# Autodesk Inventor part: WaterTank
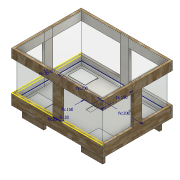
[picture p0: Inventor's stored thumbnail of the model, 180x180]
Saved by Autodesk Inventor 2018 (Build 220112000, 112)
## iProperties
Created: 2018-05
Part Number: WaterTank
Material: Generic
Document SubType Name: Modeling
Designer: arivu
Density: 1 g/cm^3
Appearance: Default
Author: arivu
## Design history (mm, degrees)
workplane "Work Plane2"
workplane "Work Plane4"
sketch "Sketch1"
  geometry: L1 (-200, 150)-(200, 150); L2 (200, 150)-(200, -150); L3 (200, -150)-(-200, -150); L4 (-200, -150)-(-200, 150); 1 further point
  constraints: 8 end point, 2 parallel, 1 horizontal, 1 perpendicular
  dimensions: "d0" = 200 distance from line of point (0, 0) L4 (= 0.5 x width); "d1" = 200 distance from line of L2 point (0, 0) (= d0); "d2" = 150 distance from line of L3 point (0, 0) (= 0.5 x height); "d3" = 150 distance from line of L1 point (0, 0) (= d2)
extrude "Extrusion1" new body sketch "Sketch1" distance "d4" = 200 (= depth); taper "d5" = 0 deg
sketch "Sketch2"
  geometry: L1 (-200, 150)-(200, 150) reference; L2 (200, -150)-(-200, -150); L3 (-200, -150)-(-200, 150); L4 (-200, 150)-(200, 150); L5 (200, 150)-(200, -150); L6 (212, -162)-(-212, -162); L7 (-212, -162)-(-212, 162); L8 (-212, 162)-(212, 162); L9 (212, 162)-(212, -162); 1 further point
  constraints: 16 end point, 4 parallel, 2 horizontal, 2 perpendicular
  dimensions: "d19" = 12 distance between parallel lines of L5 L9 (computed from osb); "d20" = 12 distance between parallel lines of L2 L6 (computed from osb); "d21" = 12 distance between parallel lines of L7 L3 (computed from osb); "d22" = 12 distance between parallel lines of L8 L1 (computed from osb)
extrude "Extrusion2" new body sketch "Sketch2" distance "d7" = 11 (= osb); taper "d8" = 0 deg
sketch "Sketch3"
  geometry: L1 (187, 137)-(87, 137); L2 (87, 137)-(87, 126); L3 (87, 126)-(187, 126); L4 (187, 126)-(187, 137); L5 (212, 162)-(-212, 162) reference; L6 (212, -162)-(212, 162) reference
  constraints: 8 end point, 2 parallel, 1 horizontal, 1 perpendicular
  dimensions: "d214" = 100 distance of L3.end L2.end; "d215" = 11 distance of L2.end L1.end (derived); "d216" = 25 distance between parallel lines of L1 L5; "d217" = 25 distance between parallel lines of L6 L4
extrude "Extrusion3" new body sketch "Sketch3" distance "d17" = 50 (= leg_lenght); taper "d18" = 0 deg
sketch "Sketch4"
  geometry: L1 (-212, -162)-(-212, 162) reference; L2 (212, -162)-(-212, -162) reference; L3 (-212, 162)-(212, 162); L4 (212, 162)-(212, -162); L5 (212, -162)-(-212, -162); L6 (-212, -162)-(-212, 162); L7 (-201, 151)-(201, 151); L8 (201, 151)-(201, -151); L9 (201, -151)-(-201, -151); L10 (-201, -151)-(-201, 151); 1 further point
  constraints: 16 end point, 4 parallel, 2 horizontal, 2 perpendicular
  dimensions: "d23" = 11 distance between parallel lines of L7 L3 (= osb); "d25" = 11 distance between parallel lines of L10 L1 (= osb); "d26" = 11 distance between parallel lines of L2 L9 (= osb); "d27" = 11 distance between parallel lines of L4 L8 (= osb)
extrude "Extrusion4" new body sketch "Sketch4" distance "d28" = 40; taper "d29" = 0 deg
sketch "Sketch5"
  geometry: L1 (0, 0)-(10.7, 0); L2 (0, 0)-(-10.7, 0); L3 (0, 0)-(0, 17.3); L4 (0, 0)-(0, -17.3); L5 (-10.7, 0)-(-10.7, 17.3); L6 (-10.7, 17.3)-(0, 17.3); L7 (0, 17.3)-(10.7, 17.3); L8 (10.7, 17.3)-(10.7, 0); L9 (10.7, -17.3)-(0, -17.3); L10 (10.7, 0)-(10.7, -17.3); L11 (0, -17.3)-(-10.7, -17.3); L12 (-10.7, -17.3)-(-10.7, 0); L13 (-161, 111)-(-143, 111); L14 (201, 151)-(-201, 151) reference; L15 (-201, 151)-(-201, -151) reference; C1 r 2.6 at (-161, 111); C2 r 2.6 at (-143, 111); C3 r 2.6 at (-161, -110); C4 r 2.6 at (-143, -110); C5 r 2.6 at (142, 111); C6 r 2.6 at (160, 111); C7 r 2.6 at (142, -110); C8 r 2.6 at (160, -110); 6 further points
  constraints: 26 end point, 8 centre point, 7 point on line, 5 horizontal, 4 perpendicular, 4 vertical, 2 coincident, 12 other
  dimensions: "d30" = 10.7 distance of L1.start L1.end; "d31" = 10.7 distance of L1.start L2.end; "d32" = 17.3 distance of L1.start L3.end; "d33" = 17.3 distance of L1.start L4.end; "d34" = 5.2 diameter of C1; "d35" = 18 distance of L13.start L13.end; "d36" = 5.2 diameter of C2; "d237" = 40 distance from line of point (-161, 111) L14; "d238" = 40 distance from line of L15 point (-161, 111); "d241" = 221 distance of L13.start C3.centre (derived); "d244" = 303 distance of L13.start C5.centre (derived)
extrude "Extrusion5" cut sketch "Sketch5" distance "d45" = 1.6; taper "d46" = 0 deg
extrude "Extrusion6" cut sketch "Sketch5" distance "d47" = 1; taper "d48" = 0 deg
workplane "Work Plane1"
workplane "Work Plane3"
sketch "Sketch6"
  geometry: L1 (-447, 336)-(-447, 347); L2 (-47, 58)-(-47, 47); L3 (-447, 347)-(-47, 347); L4 (-47, 347)-(-47, 47); L5 (-47, 47)-(-447, 47); L6 (-447, 47)-(-447, 347); 1 further point
  constraints: 12 end point, 2 parallel, 1 horizontal, 1 perpendicular
extrude "Extrusion7" new body sketch "Sketch6" distance "d49" = 11 (= osb); taper "d50" = 0 deg
sketch "Sketch7"
  geometry: L1 (427, 67)-(349, 67); L2 (349, 67)-(349, 127); L3 (349, 127)-(427, 127); L4 (427, 127)-(427, 67); L5 (347, 58)-(147, 58) reference; L6 (349, 327)-(427, 327); L7 (427, 327)-(427, 267); L8 (427, 267)-(349, 267); L9 (349, 267)-(349, 327); L10 (67, 127)-(145, 127); L11 (145, 127)-(145, 67); L12 (145, 67)-(67, 67); L13 (67, 67)-(67, 127); L14 (67, 327)-(145, 327); L15 (145, 327)-(145, 267); L16 (145, 267)-(67, 267); L17 (67, 267)-(67, 327); L18 (47, 47)-(447, 47) reference; L19 (447, 47)-(447, 347) reference; 2 further points; 1 other entity
  constraints: 32 end point, 4 parallel, 4 vertical alignment, 2 collinear, 2 horizontal, 1 perpendicular, 17 other
  dimensions: "d59" = 200 distance of L2.end L6.start (computed from height); "d62" = 282 distance of L2.end L10.start (computed from width); "d106" = 20 distance between parallel lines of L18 L1; "d107" = 20 distance between parallel lines of L19 L4
extrude "Extrusion8" cut sketch "Sketch7" distance "d65" = 1.5; taper "d66" = 0 deg
sketch "Sketch8"
  geometry: L1 (427, 67)-(349, 67) reference; L2 (427, 127)-(427, 67) reference; L3 (349, 127)-(427, 127) reference; L4 (349, 67)-(349, 127) reference; 1 further point
extrude "Extrusion9" new body sketch "Sketch8" distance "d67" = 1.5; taper "d68" = 0 deg
pattern_linear "Rectangular Pattern1" dims "d71" = 282 (computed from width), "d74" = 200 (computed from height)
shell "Shell1" dims "d6" = 3
workplane "Work Plane5"
workplane "Work Plane6"
workplane "Work Plane8"
workplane "Work Plane7"
sketch "Sketch16"
  geometry: L1 (200, 300)-(200, 0) reference; L2 (200, 0)-(200, 300); L3 (160, 300)-(160, 0); L4 (160, 300)-(160, 301); L5 (160, 301)-(200, 301); L6 (200, 301)-(200, 300); L7 (160, 0)-(160, -1); L8 (160, -1)-(200, -1); L9 (200, -1)-(200, 0); 1 further point
  constraints: 16 end point, 3 vertical, 2 collinear, 2 perpendicular, 1 point on line
  dimensions: "d172" = 1 distance of L3.start L4.end; "d173" = 40 distance of L4.end L5.end; "d174" = 1 distance of L3.end L7.end
extrude "Extrusion17" new body sketch "Sketch16" distance "d121" = 11 (= osb); taper "d122" = 0 deg
sketch "Sketch14"
  geometry: L1 (-212, 162)-(-212, -162) reference; L2 (-201, -151)-(-201, 151) reference; L3 (-212, 0)-(-201, 0); L4 (-206.5, 0)-(-206.5, -20); L5 (-206.5, -20)-(-206.5, 0); L6 (-206.5, 0)-(-206.5, 20); L7 (-206.5, 20)-(-212, 20); L8 (-206.5, 20)-(-201, 20); L9 (-206.5, -20)-(-201, -20); L10 (-206.5, -20)-(-212, -20); L11 (-212, -20)-(-212, 20); L12 (-201, 20)-(-201, -20); L13 (-212, -162)-(212, -162) reference; L14 (201, -151)-(-201, -151) reference; L15 (0, -162)-(0, -151); L16 (0, -156.5)-(-20, -156.5); L17 (-20, -156.5)-(0, -156.5); L18 (0, -156.5)-(20, -156.5); L19 (20, -156.5)-(20, -151); L20 (20, -156.5)-(20, -162); L21 (0, -162)-(20, -162); L22 (20, -151)-(0, -151); L23 (-20, -156.5)-(-20, -162); L24 (-20, -156.5)-(-20, -151); L25 (-20, -151)-(0, -151); L26 (-20, -162)-(0, -162); 1 further point
  constraints: 44 end point, 13 point on line, 8 collinear, 6 midpoint, 5 perpendicular, 1 horizontal, 1 vertical
  dimensions: "d108" = 20 distance of L4.start L4.end (= 0.5 x support); "d109" = 20 distance of L4.start L6.end (= 0.5 x support); "d115" = 20 distance of L16.start L16.end (= 0.5 x support); "d116" = 20 distance of L16.start L18.end (= 0.5 x support)
extrude "Extrusion15" new body sketch "Sketch14" stored distance "d110" = 135.8 (computed from depth, osb); taper "d111" = 0 deg
pattern_circular "Circular Pattern1" dims "d113" = 360 deg
pattern_circular "Circular Pattern2" dims "d124" = 360 deg
sketch "Sketch17"
  geometry: L1 (-1, 200)-(-1, 160); L2 (401, 200)-(401, 160); L3 (-1, 200)-(401, 200); L4 (401, 160)-(-1, 160); 1 further point
  constraints: 8 end point, 2 vertical, 1 horizontal, 1 parallel
extrude "Extrusion18" new body sketch "Sketch17" distance "d126" = 11 (= osb); taper "d127" = 0 deg
pattern_circular "Circular Pattern3" dims "d129" = 360 deg
sketch "Sketch18"
  geometry: L1 (-11, 40)-(0, 40); L2 (0, 40)-(0, 30); L3 (0, 30)-(-11, 30); L4 (-11, 30)-(-11, 40); L5 (-11, 20)-(0, 20); L6 (0, 20)-(0, 10); L7 (0, 10)-(-11, 10); L8 (-11, 10)-(-11, 20); 1 further point
  constraints: 16 end point, 4 parallel, 2 horizontal, 2 perpendicular
  dimensions: "d175" = 11 distance of L2.end L3.end (= osb); "d176" = 10 distance of L1.end L2.end; "d177" = 10 distance of L3.end L5.start; "d178" = 11 distance of L6.end L7.end (= osb); "d179" = 10 distance of L5.end L6.end
sketch "Sketch19"
  geometry: L1 (0, 0)-(0, -11); L2 (30, -11)-(20, -11); L3 (20, -11)-(20, 0); L4 (20, 0)-(30, 0); L5 (30, 0)-(30, -11); L6 (10, -11)-(0, -11); L7 (0, -11)-(0, 0); L8 (0, 0)-(10, 0); L9 (10, 0)-(10, -11); 2 further points
  constraints: 16 end point, 4 parallel, 2 horizontal, 2 perpendicular
  dimensions: "d136" = 10 distance of point (40, -11) L2.start; "d137" = 10 distance of L3.end L4.end; "d138" = 10 distance of L2.end L6.start
extrude "Extrusion19" new body sketch "Sketch18" distance "d139" = 11 (= osb); taper "d140" = 0 deg
extrude "Extrusion20" new body sketch "Sketch19" distance "d141" = 11 (= osb); taper "d142" = 0 deg
pattern_linear "Rectangular Pattern2" dims "d145" = 313 (computed from height), "d148" = 413 (computed from width)
combine "Combine3"
  body "Solid20"
  body "Solid22"
combine "Combine4"
  body "Solid16"
  body "Solid19"
combine "Combine5"
  body "Solid15"
  body "Solid18"
combine "Combine6"
  body "Solid21"
  body "Solid17"
sketch "Sketch20"
  geometry: L1 (0, 182)-(0, 142) reference; L2 (0, 142)-(5.5, 142); L3 (5.5, 142)-(5.5, 182); L4 (5.5, 182)-(0, 182); L5 (0, 182)-(0, 142); L6 (-201, 323)-(-201, 14); L7 (-407.5, 142)-(-407.5, 182); L8 (-402, 142)-(-407.5, 142); L9 (-402, 182)-(-402, 142); L10 (-407.5, 182)-(-402, 182); L11 (-181, 313)-(-181, 318.5); L12 (-221, 318.5)-(-221, 313); L13 (0, 162)-(-402, 162); L14 (-181, 11)-(-181, 5.5); L15 (-221, 5.5)-(-221, 11); L16 (-221, 318.5)-(-181, 318.5); L17 (-221, 313)-(-181, 313); L18 (-181, 5.5)-(-221, 5.5); L19 (-181, 11)-(-221, 11); 1 further point
  constraints: 36 end point, 8 symmetric about line, 5 horizontal, 2 midpoint, 1 collinear, 1 perpendicular, 1 vertical
  dimensions: "d149" = 5.5 distance of L1.end L2.end (= 0.5 x osb); "d150" = 40 distance of L2.end L3.end; "d151" = 90 deg angle of L3 L2 (derived); "d156" = 5.5 distance of L11.start L11.end (= 0.5 x osb); "d157" = 40 distance of L11.end L12.start
extrude "Extrusion23" cut sketch "Sketch20" stored distance "d159" = 11 (= osb); taper "d160" = 0 deg
extrude "Extrusion25" new body sketch "Sketch20" stored distance "d163" = 40; taper "d164" = 0 deg
combine "Combine7"
combine "Combine8"
  body "Solid23"
sketch "Sketch22"
  geometry: L1 (5.5, 0)-(5.5, 40) reference; L2 (0, 0)-(5.5, 0) reference; L3 (0, 40)-(0, 0) reference; L4 (5.5, 40)-(0, 40) reference; L5 (-221, 171)-(-181, 171) reference; L6 (-221, 176.5)-(-221, 171) reference; L7 (-221, 176.5)-(-181, 176.5) reference; L8 (-181, 171)-(-181, 176.5) reference; L9 (-407.5, 0)-(-407.5, 40) reference; L10 (-402, 0)-(-407.5, 0) reference; L11 (-402, 40)-(-402, 0) reference; L12 (-407.5, 40)-(-402, 40) reference; L13 (-181, -131)-(-181, -136.5) reference; L14 (-181, -136.5)-(-221, -136.5) reference; L15 (-221, -136.5)-(-221, -131) reference; L16 (-181, -131)-(-221, -131) reference; 1 further point
extrude "Extrusion26" join sketch "Sketch22" distance "d165" = 40; taper "d166" = 0 deg
sketch "Sketch23"
  geometry: L1 (-20, 151)-(20, 151) reference; L2 (20, 151)-(20, 156.5) reference; L3 (20, 156.5)-(-20, 156.5) reference; L4 (-20, 156.5)-(-20, 151) reference; L5 (206.5, -20)-(206.5, 20) reference; L6 (206.5, 20)-(201, 20) reference; L7 (201, 20)-(201, -20) reference; L8 (201, -20)-(206.5, -20) reference; L9 (20, -156.5)-(20, -151) reference; L10 (20, -151)-(-20, -151) reference; L11 (-20, -151)-(-20, -156.5) reference; L12 (-20, -156.5)-(20, -156.5) reference; L13 (-206.5, 20)-(-206.5, -20) reference; L14 (-206.5, -20)-(-201, -20) reference; L15 (-201, -20)-(-201, 20) reference; L16 (-201, 20)-(-206.5, 20) reference; 1 further point
  node "Projected Loop3"
  node "Projected Loop4"
  node "Projected Loop5"
  node "Projected Loop6"
extrude "Extrusion27" new body sketch "Sketch23" stored distance "d167" = 40; taper "d168" = 0 deg
combine "Combine9"
  body "Solid24"
extrude "Extrusion28" new body sketch "Sketch23" stored distance "d169" = 40; taper "d170" = 0 deg
combine "Combine10"
sketch "Sketch26"
  geometry: L1 (0, 0)-(424, 0) reference; L2 (424, 0)-(424, 40) reference; L3 (0, 40)-(424, 40) reference; L4 (0, 0)-(0, 40) reference; L5 (0, 40)-(11, 40); L6 (11, 40)-(11, 30); L7 (11, 30)-(0, 30); L8 (0, 30)-(0, 40); L9 (0, 20)-(11, 20); L10 (11, 20)-(11, 10); L11 (11, 10)-(0, 10); L12 (0, 10)-(0, 20); L13 (0, 10)-(11, 10); L14 (11, 10)-(11, 0); L15 (11, 0)-(0, 0); L16 (0, 0)-(0, 10); L17 (0, 30)-(11, 30); L18 (11, 30)-(11, 20); L19 (11, 20)-(0, 20); L20 (0, 20)-(0, 30); L21 (424, 40)-(413, 40); L22 (413, 40)-(413, 30); L23 (413, 30)-(424, 30); L24 (424, 30)-(424, 40); L25 (413, 30)-(424, 30); L26 (424, 30)-(424, 20); L27 (424, 20)-(413, 20); L28 (413, 20)-(413, 30); L29 (413, 20)-(424, 20); L30 (424, 20)-(424, 10); L31 (424, 10)-(413, 10); L32 (413, 10)-(413, 20); L33 (413, 10)-(424, 10); L34 (424, 10)-(424, 0); L35 (424, 0)-(413, 0); L36 (413, 0)-(413, 10)
  constraints: 64 end point, 16 parallel, 8 horizontal, 8 perpendicular, 1 midpoint, 1 point on line
  dimensions: "d180" = 11 distance of L6.end L7.end (= osb); "d181" = 10 distance of L5.end L6.end; "d182" = 11 distance of L10.end L11.end (= osb); "d183" = 10 distance of L9.end L10.end; "d184" = 10 distance of L9.start L7.end; "d185" = 11 distance of L14.end L15.end (= osb); "d186" = 11 distance of L23.end L22.end (= osb); "d187" = 10 distance of L22.end L21.end; "d188" = 11 distance of L26.end L27.end (= osb); "d189" = 10 distance of L25.end L26.end; "d190" = 11 distance of L30.end L31.end (= osb); "d191" = 10 distance of L29.end L30.end
  node "Projected Loop7"
extrude "Extrusion29" new body sketch "Sketch26" distance "d192" = 11 (= osb); taper "d193" = 0 deg
extrude "Extrusion30" new body sketch "Sketch26" distance "d194" = 11 (= osb); taper "d195" = 0 deg
extrude "Extrusion31" new body sketch "Sketch26" distance "d196" = 11 (= osb); taper "d197" = 0 deg
extrude "Extrusion32" new body sketch "Sketch26" distance "d198" = 11 (= osb); taper "d199" = 0 deg
workplane "Work Plane9"
workplane "Work Plane10"
split "Split1"
  body "Solid4"
split "Split2"
  body "Solid30"
split "Split3"
  body "Solid33"
combine "Combine11"
  body "Solid28"
  body "Solid26"
combine "Combine12"
  body "Solid27"
combine "Combine13"
combine "Combine14"
  body "Solid29"
combine "Combine15"
sketch "Sketch27"
  geometry: L1 (413, 10)-(402, 10) reference; L2 (402, 20)-(413, 20) reference; L3 (413, 30)-(402, 30) reference; L4 (0, 10)-(-11, 10) reference; L5 (-11, 20)-(0, 20) reference; L6 (0, 30)-(-11, 30) reference; L7 (402, 10)-(413, 10); L8 (413, 10)-(413, 0); L9 (413, 0)-(402, 0); L10 (402, 0)-(402, 10); L11 (413, 10)-(402, 10); L12 (402, 10)-(402, 20); L13 (402, 20)-(413, 20); L14 (413, 20)-(413, 10); L15 (413, 20)-(402, 20); L16 (402, 20)-(402, 30); L17 (402, 30)-(413, 30); L18 (413, 30)-(413, 20); L19 (413, 30)-(402, 30); L20 (402, 30)-(402, 40); L21 (402, 40)-(413, 40); L22 (413, 40)-(413, 30); L23 (0, 10)-(-11, 10); L24 (-11, 10)-(-11, 0); L25 (-11, 0)-(0, 0); L26 (0, 0)-(0, 10); L27 (0, 10)-(-11, 10); L28 (-11, 10)-(-11, 20); L29 (-11, 20)-(0, 20); L30 (0, 20)-(0, 10); L31 (0, 20)-(-11, 20); L32 (-11, 20)-(-11, 30); L33 (-11, 30)-(0, 30); L34 (0, 30)-(0, 20); L35 (0, 30)-(-11, 30); L36 (-11, 30)-(-11, 40); L37 (-11, 40)-(0, 40); L38 (0, 40)-(0, 30); 1 further point
  constraints: 64 end point, 16 parallel, 8 horizontal, 8 perpendicular, 2 point on line
  dimensions: "d200" = 11 distance of L8.end L9.end (= osb); "d201" = 10 distance of L7.end L8.end; "d202" = 11 distance of L20.end L21.end (= osb); "d203" = 10 distance of L19.end L20.end; "d204" = 11 distance of L25.end L24.end (= osb); "d205" = 10 distance of L24.end L23.end
extrude "Extrusion33" new body sketch "Sketch27" distance "d206" = 11 (= osb); taper "d207" = 0 deg
extrude "Extrusion34" new body sketch "Sketch27" distance "d208" = 11 (= osb); taper "d209" = 0 deg
extrude "Extrusion35" new body sketch "Sketch27" distance "d210" = 11 (= osb); taper "d211" = 0 deg
extrude "Extrusion36" new body sketch "Sketch27" distance "d212" = 11 (= osb); taper "d213" = 0 deg
combine "Combine16"
  body "Solid36"
  body "Solid38"
combine "Combine17"
  body "Solid37"
combine "Combine18"
  body "Solid39"
combine "Combine19"
combine "Combine20"
pattern_linear "Rectangular Pattern3" dims "d220" = 274 (derived), "d223" = 263 (derived)
sketch "Sketch28"
  geometry: L1 (-187, 126)-(-87, 126); L2 (-187, -126)-(-187, -137); L3 (167, 137)-(107, 137); L4 (107, 137)-(107, 126); L5 (107, 126)-(167, 126); L6 (167, 126)-(167, 137); L7 (-167, 137)-(-167, 126); L8 (-107, 137)-(-167, 137); L9 (-107, 126)-(-107, 137); L10 (-167, 126)-(-107, 126); L11 (107, -126)-(107, -137); L12 (167, -126)-(107, -126); L13 (167, -137)-(167, -126); L14 (107, -137)-(167, -137); L15 (-167, -126)-(-167, -137); L16 (-107, -126)-(-167, -126); L17 (-107, -137)-(-107, -126); L18 (-167, -137)-(-107, -137); 1 further point
  constraints: 36 end point, 2 horizontal, 2 parallel, 1 perpendicular, 1 vertical, 24 other
  dimensions: "d225" = 60 distance of L5.end L4.end; "d226" = 11 distance of L4.end L3.end (derived); "d229" = 274 distance of L3.end L7.start (derived); "d232" = 263 distance of L3.end L11.start (derived)
extrude "Extrusion37" new body sketch "Sketch28" distance "d235" = 11 (derived); taper "d236" = 0 deg
combine "Combine21"
combine "Combine22"
  body "Solid40"
sketch "Sketch29"
  geometry: L1 (20, -151)-(212, -151) reference; L2 (212, 151)-(20, 151) reference; L3 (-212, 162)-(212, 162) reference; L4 (-212, -151)-(-212, 151) reference; L5 (-201, -20)-(-201, -151) reference; L6 (-212, -162)-(212, -162) reference; L7 (-20, -151)-(-212, -151) reference; L8 (212, 151)-(212, -151) reference; L9 (201, -151)-(201, -20) reference; L10 (201, 20)-(201, 151) reference; L11 (-201, 151)-(-201, 20) reference; L12 (-212, 151)-(-20, 151) reference; L13 (-20, -151)-(-70, -151); L14 (-70, -151)-(-70, -162); L15 (-70, -162)-(-20, -162); L16 (-20, -162)-(-20, -151); L17 (20, -151)-(70, -151); L18 (70, -151)-(70, -162); L19 (70, -162)-(20, -162); L20 (20, -162)-(20, -151); L21 (-20, 151)-(-70, 151); L22 (-70, 151)-(-70, 162); L23 (-70, 162)-(-20, 162); L24 (-20, 162)-(-20, 151); L25 (20, 151)-(70, 151); L26 (70, 151)-(70, 162); L27 (70, 162)-(20, 162); L28 (20, 162)-(20, 151); L29 (201, 20)-(212, 20); L30 (212, 20)-(212, 70); L31 (212, 70)-(201, 70); L32 (201, 70)-(201, 20); L33 (201, -20)-(212, -20); L34 (212, -20)-(212, -70); L35 (212, -70)-(201, -70); L36 (201, -70)-(201, -20); L37 (-201, 20)-(-212, 20); L38 (-212, 20)-(-212, 70); L39 (-212, 70)-(-201, 70); L40 (-201, 70)-(-201, 20); L41 (-201, -20)-(-212, -20); L42 (-212, -20)-(-212, -70); L43 (-212, -70)-(-201, -70); L44 (-201, -70)-(-201, -20); 1 further point
  constraints: 64 end point, 16 parallel, 8 horizontal, 8 perpendicular, 2 point on line
  dimensions: "d247" = 50 distance of L15.end L14.end; "d248" = 50 distance of L18.end L19.end; "d249" = 50 distance of L22.end L23.end; "d250" = 11 distance of L21.end L22.end (derived); "d251" = 50 distance of L27.end L26.end; "d252" = 11 distance of L26.end L25.end (derived); "d253" = 11 distance of L31.end L30.end (derived); "d254" = 50 distance of L30.end L29.end; "d255" = 11 distance of L34.end L35.end (derived); "d256" = 50 distance of L33.end L34.end; "d257" = 11 distance of L38.end L39.end (derived); "d258" = 50 distance of L37.end L38.end; "d259" = 11 distance of L43.end L42.end (derived); "d260" = 50 distance of L42.end L41.end
extrude "Extrusion39" new body sketch "Sketch29" distance "d263" = 11 (derived); taper "d264" = 0 deg
extrude "Extrusion40" new body sketch "Sketch29" distance "d265" = 11 (derived); taper "d266" = 0 deg
extrude "Extrusion41" new body sketch "Sketch29" distance "d267" = 11 (derived); taper "d268" = 0 deg
extrude "Extrusion42" new body sketch "Sketch29" distance "d269" = 11 (derived); taper "d270" = 0 deg
combine "Combine24"
  body "Solid42"
combine "Combine25"
  body "Solid43"
combine "Combine26"
  body "Solid44"
combine "Combine27"
  body "Solid45"
combine "Combine28"
extrude "Extrusion43" new body sketch "Sketch28" distance "d271" = 11 (derived); taper "d272" = 0 deg
extrude "Extrusion44" new body sketch "Sketch28" distance "d273" = 11 (derived); taper "d274" = 0 deg
extrude "Extrusion45" new body sketch "Sketch28" distance "d275" = 11 (derived); taper "d276" = 0 deg
combine "Combine29"
  body "Solid50"
combine "Combine30"
  body "Solid51"
combine "Combine31"
  body "Solid49"
combine "Combine32"
extrude "Extrusion46" new body sketch "Sketch23" stored distance "d277" = 11 (derived); taper "d278" = 0 deg
extrude "Extrusion47" new body sketch "Sketch23" stored distance "d279" = 11 (derived); taper "d280" = 0 deg
extrude "Extrusion48" new body sketch "Sketch23" stored distance "d281" = 11 (derived); taper "d282" = 0 deg
extrude "Extrusion49" new body sketch "Sketch23" stored distance "d283" = 11 (derived); taper "d284" = 0 deg
extrude "Extrusion50" new body sketch "Sketch22" stored distance "d285" = 11 (derived); taper "d286" = 0 deg
extrude "Extrusion51" new body sketch "Sketch22" stored distance "d287" = 11 (derived); taper "d288" = 0 deg
extrude "Extrusion52" new body sketch "Sketch22" stored distance "d289" = 11 (derived); taper "d290" = 0 deg
extrude "Extrusion53" new body sketch "Sketch22" stored distance "d291" = 11 (derived); taper "d292" = 0 deg
combine "Combine33"
  body "Solid57"
  body "Solid58"
  body "Solid55"
  body "Solid56"
workplane "Work Plane11"
split "Split4"
  body "Solid52"
split "Split5"
  body "Solid12"
sketch "Sketch9"
  geometry: 1 further point
sketch "Sketch10"
  geometry: L1 (0, 0)-(197, 0) reference; L2 (198.945, 147.013)-(197, 237); L3 (163.191, 140.195)-(161.385, 153.83); L4 (198.945, 147.013)-(196.682, 60.73); L5 (163.191, 140.195)-(163.191, 160.195); L6 (163.191, 160.195)-(197, 160.195); L7 (197, 160.195)-(197, 237); L8 (161.385, 153.83)-(163.191, 40.195); L9 (163.191, 40.195)-(197, 40.733); L10 (197, 40.733)-(196.682, 60.73); L11 (162.288, 147.013)-(198.945, 147.013); L12 (198.945, 147.013)-(197, 137.204); L13 (197, 137.204)-(164.164, 132.854); L14 (164.164, 132.854)-(162.288, 147.013); L15 (162.288, 147.013)-(160.975, 156.926); L16 (160.975, 156.926)-(197, 161.698); L17 (198.945, 147.013)-(197, 161.698); 4 further points; 2 other entities
  constraints: 32 end point, 5 perpendicular, 3 point on line, 2 vertical, 1 collinear, 1 horizontal, 1 midpoint, 6 other
  dimensions: "d90" = 150 distance of point (197, 297) L2.start (= 0.5 x height); "d93" = 120 distance of L8.end L5.end; "d94" = 10 distance of L2.start L12.end; "d95" = 10 distance of L11.start L15.end
extrude "Extrusion12" new body sketch "Sketch10" distance "d96" = 40; taper "d97" = 0 deg
extrude "Extrusion13" new body sketch "Sketch10" distance "d98" = 40; taper "d99" = 0 deg
sketch "Sketch13"
  geometry: L1 (-40, 0)-(-25, 0); L2 (-25, 0)-(-40, 41.164); L3 (0, 41.164)-(-394, 41.164) reference; L4 (-40, 41.164)-(-40, 0); 1 further point
  constraints: 6 end point, 1 point on line
  dimensions: "d100" = 15 distance of L1.start L1.end
extrude "Extrusion14" cut sketch "Sketch13" stored distance "d101" = 40; taper "d102" = 0 deg
shell "Shell4" dims "d103" = 1
fillet "Fillet3" dims "d105" = 4
body "Solid1"
body "Solid2"
body "Solid3"
body "Solid5"
body "Solid6"
body "Solid8"
body "Solid9"
body "Solid10"
body "Solid13"
feature "Pattern of Solid13:1"
body "Solid14"
feature "Pattern of Solid15:2"
feature "Pattern of Solid15:3"
feature "Pattern of Solid15:4"
feature "Pattern of Solid16:5"
feature "Pattern of Solid16:6"
feature "Pattern of Solid16:7"
body "Solid25"
feature "Pattern of Solid3:8"
body "Solid46"
feature "Pattern of Solid3:9"
body "Solid47"
feature "Pattern of Solid3:10"
body "Solid48"
feature "Pattern of Solid10:11"
body "Solid53"
body "Solid54"
body "Solid59"
body "Solid60"
body "Solid31"
body "Solid32"
body "Solid34"
body "Solid35"
body "Solid61"
body "Solid62"
body "Solid63"
body "Solid64"
other parameters: "depth" = 200 [user parameter; used in 2 equation terms], "osb" = 11 [user parameter; used in 37 equation terms], "leg_lenght" = 50 [user parameter; used in 1 equation term], "d76" = 22, "d77" = 7.8, "d78" = 18.8, "d131" = 1, "d132" = 1, "d133" = 1, "d171" = 1, "d293" = 2
